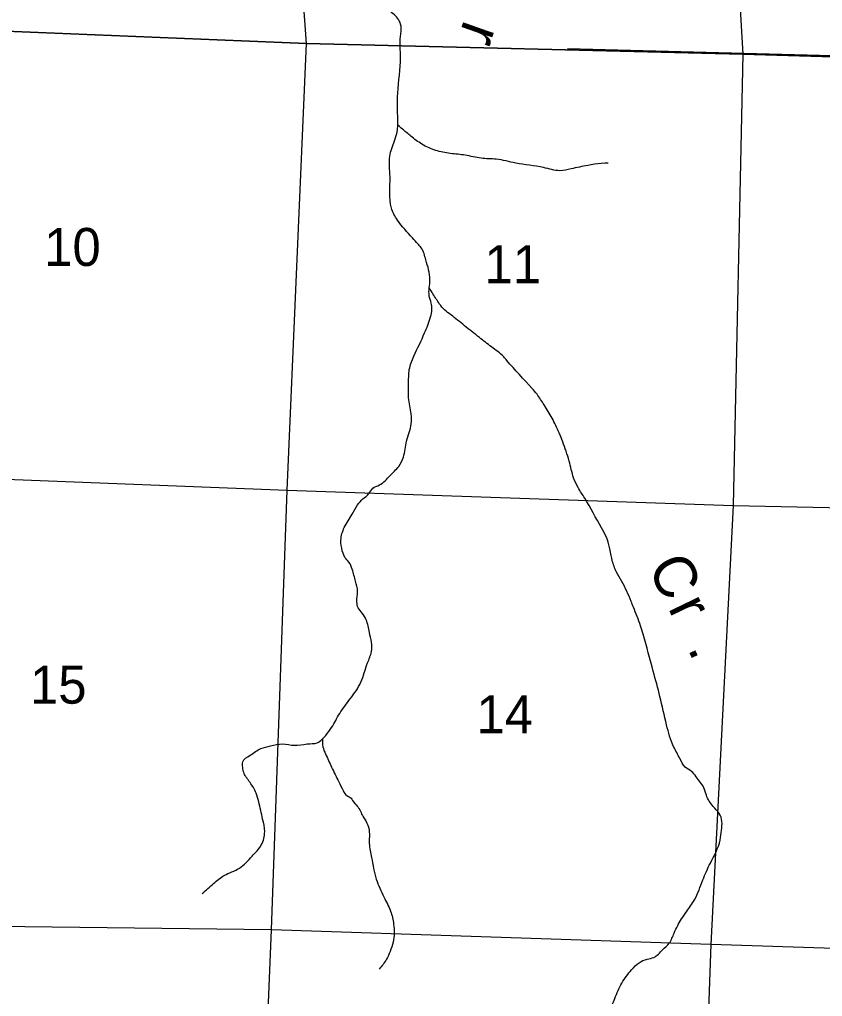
# Model space of a CAD drawing. Extents: x 1219626 to 1426462, y 456797 to 752399.
# Drawn here: x 1328623 to 1338132, y 610689 to 622257 of the extents above; entities that cross this region are included whole.
import ezdxf

# ---------------------------------------------------------------- set-up
doc = ezdxf.new("R2010")
doc.units = 0
for name, color, linetype in [('Masks', 7, 'Continuous'), ('Narrow River Creek and Branch and Slough', 7, 'Continuous'), ('Narrow River Creek and Branch and Slough Text', 7, 'Continuous'), ('Section Lines', 7, 'Continuous'), ('Section Numbers', 7, 'Continuous'), ('State Routes Highway Center Lines', 7, 'Continuous'), ('Uninventoried Roads and Features', 7, 'Continuous')]:
    doc.layers.add(name, color=color, linetype=linetype)

msp = doc.modelspace()

# ---------------------------------------------------------------- linework, layer by layer
at = {"layer": 'Masks'}
msp.add_line((1333511, 621937), (1334532, 621912), dxfattribs=at)
at = {"layer": 'Narrow River Creek and Branch and Slough'}
for points in [[(1330787, 611909), (1330921, 612027), (1331046, 612122), (1331227, 612208), (1331376, 612350), (1331486, 612483), (1331526, 612641), (1331502, 612790), (1331455, 612995), (1331424, 613097), (1331353, 613223), (1331282, 613333), (1331266, 613403), (1331266, 613466), (1331353, 613545), (1331479, 613624), (1331596, 613655), (1331738, 613679), (1331879, 613663), (1332029, 613679), (1332147, 613694), (1332249, 613781), (1332319, 613875), (1332414, 614040), (1332539, 614213), (1332665, 614410), (1332744, 614638), (1332791, 614772), (1332767, 615000), (1332728, 615149), (1332681, 615228), (1332634, 615291), (1332618, 615361), (1332626, 615487), (1332602, 615605), (1332563, 615747), (1332524, 615833), (1332477, 615888), (1332445, 615967), (1332429, 616093), (1332469, 616242), (1332563, 616400), (1332626, 616510), (1332689, 616581), (1332760, 616643), (1332807, 616706), (1332885, 616746), (1333011, 616856), (1333113, 616966), (1333168, 617076), (1333207, 617265), (1333262, 617469), (1333262, 617587), (1333231, 617776), (1333231, 617933), (1333239, 618114), (1333294, 618271), (1333420, 618546), (1333490, 618735), (1333506, 618822), (1333498, 618900), (1333475, 618987), (1333483, 619175), (1333435, 619411), (1333380, 619553), (1333341, 619600), (1333278, 619671), (1333097, 619883), (1333027, 620025), (1333011, 620394), (1333008, 620639), (1333063, 620820), (1333094, 620922), (1333102, 621072), (1333102, 621386), (1333134, 621811), (1333134, 622055), (1333141, 622180), (1333110, 622259), (1333063, 622314), (1333008, 622361), (1332992, 622408), (1332984, 622495), (1333008, 622550), (1333016, 622605), (1333063, 622707), (1333102, 622731), (1333141, 622794), (1333228, 622817), (1333314, 622864), (1333377, 622904)], [(1335594, 620556), (1335432, 620545), (1335353, 620530), (1335154, 620488), (1335023, 620467), (1334829, 620504), (1334499, 620556), (1334269, 620603), (1334090, 620614), (1333902, 620650), (1333724, 620671), (1333551, 620708), (1333388, 620781), (1333257, 620876), (1333158, 620960), (1333103, 621007)], [(1333891, 618631), (1333729, 618762), (1333656, 618819), (1333598, 618888), (1333519, 619008), (1333477, 619077)], [(1334227, 606816), (1334400, 606831), (1334614, 606879), (1334840, 606952), (1334997, 607057), (1335060, 607120), (1335102, 607293), (1335191, 607691), (1335217, 607848), (1335264, 607927), (1335432, 608110), (1335568, 608252), (1335631, 608315), (1335636, 608415), (1335599, 608493), (1335515, 608582), (1335474, 608629), (1335479, 608708), (1335547, 608808), (1335699, 608939), (1335851, 609080), (1335929, 609169), (1335982, 609238), (1336013, 609311), (1336008, 609379), (1335966, 609494), (1335935, 609573), (1335788, 609862), (1335746, 609941), (1335657, 610088), (1335573, 610229), (1335547, 610318), (1335542, 610444), (1335584, 610523), (1335641, 610591), (1335673, 610664), (1335756, 610848), (1335872, 611005), (1335961, 611089), (1336055, 611131), (1336134, 611152), (1336238, 611241), (1336317, 611320), (1336375, 611440), (1336417, 611529), (1336464, 611608), (1336521, 611692), (1336616, 611833), (1336715, 612069), (1336804, 612269), (1336920, 612541), (1336935, 612657), (1336941, 612762), (1336909, 612856), (1336836, 612940), (1336757, 613071), (1336726, 613160), (1336684, 613228), (1336637, 613291), (1336579, 613354), (1336506, 613406), (1336443, 613506), (1336369, 613647), (1336286, 613904), (1336207, 614240), (1336128, 614539), (1336008, 614979), (1335977, 615079), (1335893, 615299), (1335866, 615367), (1335756, 615603), (1335694, 615713), (1335641, 615855), (1335610, 616007), (1335573, 616127), (1335515, 616237), (1335316, 616588), (1335238, 616714), (1335185, 616830), (1335133, 617029), (1335096, 617144), (1335013, 617364), (1334929, 617537), (1334834, 617695), (1334751, 617820), (1334693, 617889), (1334394, 618219), (1334358, 618261), (1334211, 618381), (1334069, 618491), (1333891, 618631)], [(1332209, 613734), (1332215, 613645), (1332246, 613561), (1332319, 613404), (1332403, 613231), (1332456, 613126), (1332497, 613068), (1332550, 613037), (1332566, 613011), (1332623, 612943), (1332691, 612817), (1332749, 612717), (1332765, 612502), (1332791, 612334), (1332848, 612078), (1332938, 611868), (1332979, 611784), (1333016, 611700), (1333053, 611543), (1333048, 611333), (1333011, 611223), (1332969, 611129), (1332880, 611013)]]:
    msp.add_spline(points, degree=3, dxfattribs=at)
at = {"layer": 'Section Lines'}
for p, q in [((1332020, 621974), (1331696, 626597)), ((1336914, 626446), (1337188, 621846)), ((1332020, 621974), (1326722, 622188)), ((1331794, 616684), (1332020, 621974)), ((1337188, 621846), (1332020, 621974)), ((1337188, 621846), (1337075, 616502)), ((1342237, 621702), (1337188, 621846)), ((1326488, 616890), (1331794, 616684)), ((1331608, 611478), (1331794, 616684)), ((1331794, 616684), (1337075, 616502)), ((1337075, 616502), (1336811, 611304)), ((1337075, 616502), (1342329, 616399)), ((1331608, 611478), (1326335, 611541)), ((1331377, 606220), (1331608, 611478)), ((1336811, 611304), (1331608, 611478)), ((1336811, 611304), (1336624, 606037)), ((1342115, 611138), (1336811, 611304))]:
    msp.add_line(p, q, dxfattribs=at)
at = {"layer": 'State Routes Highway Center Lines'}
for p, q in [((1326722, 622188), (1332020, 621974)), ((1332020, 621974), (1337188, 621846)), ((1337188, 621846), (1342237, 621702))]:
    msp.add_line(p, q, dxfattribs=at)
at = {"layer": 'Uninventoried Roads and Features'}
msp.add_line((1335114, 621912), (1338936, 621812), dxfattribs=at)

# ---------------------------------------------------------------- texts
at = {"layer": 'Narrow River Creek and Branch and Slough Text'}
for s, rotation, p in [('r', 250.5441, (1333892, 622268)), ('C', 297.2384, (1336053, 615770)), ('r', 295.7446, (1336298, 615294)), ('.', 294.6335, (1336531, 614811))]:
    msp.add_text(s, height=500, rotation=rotation, dxfattribs=at).set_placement(p)
at = {"layer": 'Section Numbers'}
for s, p in [('10', (1328915, 619339)), ('11', (1334129, 619135)), ('15', (1328747, 614156)), ('14', (1334034, 613806))]:
    msp.add_text(s, height=450, rotation=360, dxfattribs=at).set_placement(p)

doc.saveas('drawing.dxf')
